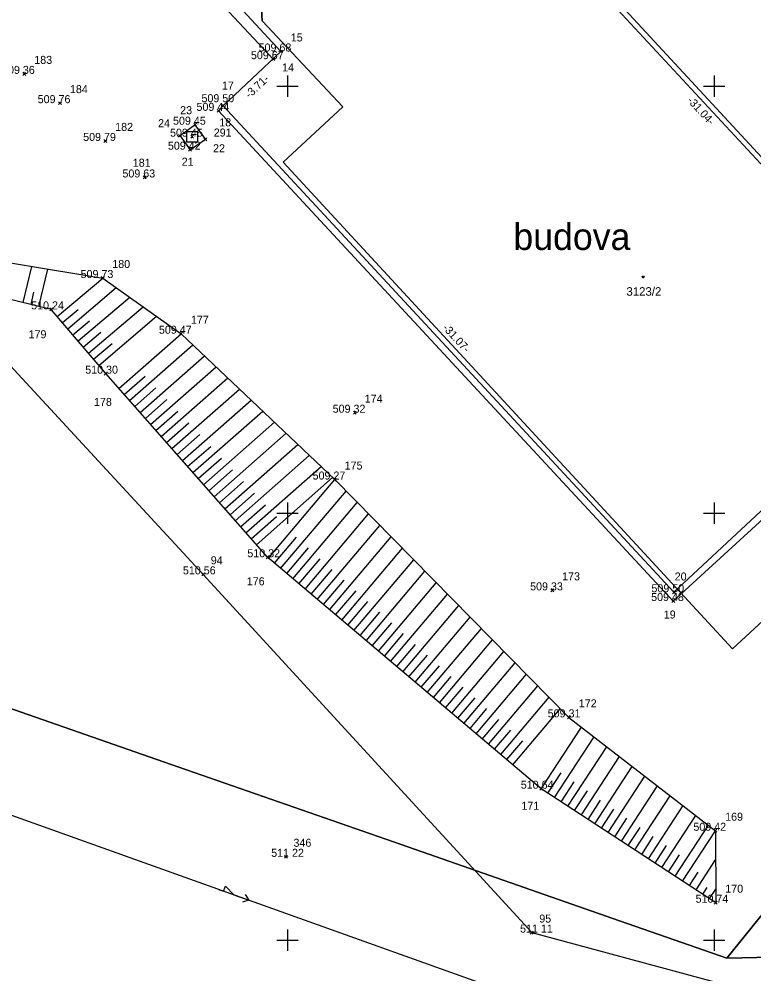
# Model space of a CAD drawing. Extents: x -408550 to -407654, y -1233019 to -1231230.
# Drawn here: x -407992.57 to -407958.14, y -1232101.58 to -1232056.86 of the extents above; entities that cross this region are included whole.
import ezdxf

# ---------------------------------------------------------------- set-up
doc = ezdxf.new("R2010")
doc.units = 0
for name, color, linetype in [('Level 1', 7, 'Continuous'), ('Level 11', 7, 'Continuous'), ('Level 12', 7, 'Continuous'), ('Level 13', 7, 'Continuous'), ('Level 16', 7, 'Continuous'), ('Level 20', 7, 'Continuous'), ('Level 22', 7, 'Continuous'), ('Level 23', 7, 'Continuous'), ('Level 25', 7, 'Continuous'), ('Level 26', 7, 'Continuous'), ('Level 27', 7, 'Continuous'), ('Level 4', 7, 'Continuous'), ('Level 40', 7, 'Continuous')]:
    doc.layers.add(name, color=color, linetype=linetype)

msp = doc.modelspace()

# ---------------------------------------------------------------- linework, layer by layer
at = {"layer": 'Level 1'}
for p, q in [((-407980, -1232059.5), (-407980, -1232060.5)), ((-407960, -1232059.5), (-407960, -1232060.5)), ((-407980.5, -1232060), (-407979.5, -1232060)), ((-407960.5, -1232060), (-407959.5, -1232060)), ((-407980, -1232079.5), (-407980, -1232080.5)), ((-407960, -1232079.5), (-407960, -1232080.5)), ((-407980.5, -1232080), (-407979.5, -1232080)), ((-407960.5, -1232080), (-407959.5, -1232080)), ((-407980, -1232099.5), (-407980, -1232100.5)), ((-407960, -1232099.5), (-407960, -1232100.5)), ((-407980.5, -1232100), (-407979.5, -1232100)), ((-407960.5, -1232100), (-407959.5, -1232100))]:
    msp.add_line(p, q, dxfattribs=at)
for points in [[(-407865.11, -1232098.76), (-407959.41, -1232100.85), (-407908.02, -1232037.31), (-407927.08, -1232021.88), (-407925.98, -1232020.38), (-407922.27, -1232015.79), (-407913.48, -1232004.91), (-407905.89, -1231995.51), (-407896.46, -1231983.85)], [(-407908.02, -1232037.31), (-407959.41, -1232100.85), (-407964.75, -1232098.99), (-407974.67, -1232095.53), (-407985.8, -1232091.65), (-408004.8, -1232085.03), (-408023.96, -1232078.34), (-408035.27, -1232074.4), (-408044.77, -1232071.09)], [(-408044.77, -1232071.09), (-408035.27, -1232074.4), (-408023.96, -1232078.34), (-408004.8, -1232085.03), (-407985.8, -1232091.65), (-407974.67, -1232095.53), (-407964.75, -1232098.99), (-407959.41, -1232100.85), (-407865.11, -1232098.76), (-407866.39, -1232098.97), (-407901.79, -1232106.39), (-407899.44, -1232117.51), (-407894.61, -1232140.35), (-407874.15, -1232135.48), (-407862.74, -1232131.55), (-407855.39, -1232125.61), (-407852.28, -1232122.69), (-407848.72, -1232121.07), (-407838.47, -1232120.5), (-407847.32, -1232123.67), (-407848.36, -1232134.5), (-407841.61, -1232145.17), (-407846.34, -1232175.35)]]:
    msp.add_lwpolyline(points, dxfattribs=at)
for points in [[(-407983.55, -1232015.52), (-407983.6, -1232014.52), (-407981.73, -1232014.41), (-407981.67, -1232015.42), (-407970.32, -1232014.9), (-407969.16, -1232040.17), (-407975.2, -1232040.45), (-407974.95, -1232045.12), (-407973.55, -1232045.08), (-407973.31, -1232049.36), (-407974.72, -1232049.44), (-407974.48, -1232053.95), (-407972.3, -1232056.28), (-407968.04, -1232052.23), (-407946.92, -1232075.07), (-407959.14, -1232086.36), (-407980.2, -1232063.57), (-407977.4, -1232060.97), (-407981.18, -1232056.94), (-407981.8, -1232045.69), (-407982.07, -1232040.75), (-407985.47, -1232040.9), (-407986.59, -1232015.66)], [(-407983.6, -1232014.52), (-407983.55, -1232015.52), (-407986.59, -1232015.66), (-407985.47, -1232040.9), (-407982.07, -1232040.75), (-407981.8, -1232045.69), (-407981.18, -1232056.94), (-407977.4, -1232060.97), (-407980.2, -1232063.57), (-407959.14, -1232086.36), (-407946.92, -1232075.07), (-407968.04, -1232052.23), (-407972.3, -1232056.28), (-407974.48, -1232053.95), (-407974.72, -1232049.44), (-407973.31, -1232049.36), (-407973.55, -1232045.08), (-407974.95, -1232045.12), (-407975.2, -1232040.45), (-407969.16, -1232040.17), (-407970.32, -1232014.9), (-407981.67, -1232015.42), (-407981.73, -1232014.41)], [(-407963.309, -1232068.905), (-407963.287, -1232068.943), (-407963.309, -1232068.981), (-407963.352, -1232068.981), (-407963.374, -1232068.943), (-407963.352, -1232068.905)]]:
    msp.add_lwpolyline(points, close=True, dxfattribs=at)
at = {"layer": 'Level 11'}
msp.add_lwpolyline([(-407989.46, -1232013.01), (-407973.21, -1232012.23), (-407971.98, -1232037.5), (-407977.95, -1232037.78), (-407977.733, -1232042.415), (-407976.39, -1232042.37), (-407976.14, -1232046.74), (-407977.45, -1232046.87), (-407977.009, -1232051.318), (-407974.962, -1232053.765), (-407970.82, -1232049.62), (-407949.71, -1232072.37), (-407961.89, -1232083.71), (-407983.01, -1232060.92), (-407980.3, -1232058.38), (-407984.06, -1232054.32), (-407985.01, -1232038.14), (-407988.32, -1232038.28)], close=True, dxfattribs=at)
at = {"layer": 'Level 12'}
msp.add_lwpolyline([(-408056.73, -1232038.31), (-408035.18, -1232049.43), (-408016.67, -1232058.98), (-407995.64, -1232070.23), (-407983.94, -1232082.87), (-407968.55, -1232099.65), (-407955.47, -1232103.17), (-407935.56, -1232108.32), (-407927.78, -1232110.15), (-407922.43, -1232090.45), (-407918.07, -1232073.76), (-407912.71, -1232053.79), (-407910.82, -1232047.19), (-407908.67, -1232042.13), (-407906.88, -1232038.31), (-407908.34, -1232037.12), (-407921.23, -1232026.55), (-407939.09, -1232011.64)], dxfattribs=at)
at = {"layer": 'Level 13'}
for p, q in [((-407992.374, -1232070.143), (-407991.965, -1232068.448)), ((-407992.374, -1232070.143), (-407991.965, -1232068.448)), ((-407991.644, -1232070.319), (-407991.223, -1232068.569)), ((-407991.644, -1232070.319), (-407991.223, -1232068.569)), ((-407990.778, -1232070.793), (-407988.65, -1232068.99)), ((-407992.009, -1232070.231), (-407991.871, -1232069.657)), ((-407992.009, -1232070.231), (-407991.871, -1232069.657)), ((-407990.293, -1232071.365), (-407988.019, -1232069.439)), ((-407989.808, -1232071.937), (-407987.388, -1232069.887)), ((-407990.536, -1232071.079), (-407989.803, -1232070.458)), ((-407989.324, -1232072.51), (-407986.758, -1232070.336)), ((-407990.051, -1232071.651), (-407989.269, -1232070.989)), ((-407988.839, -1232073.082), (-407986.127, -1232070.784)), ((-407989.566, -1232072.223), (-407988.736, -1232071.52)), ((-407987.894, -1232074.169), (-407984.98, -1232071.6)), ((-407989.081, -1232072.796), (-407988.202, -1232072.051)), ((-407987.398, -1232074.731), (-407984.434, -1232072.118)), ((-407986.902, -1232075.294), (-407983.887, -1232072.636)), ((-407986.407, -1232075.857), (-407983.341, -1232073.155)), ((-407987.646, -1232074.45), (-407986.667, -1232073.587)), ((-407985.911, -1232076.419), (-407982.795, -1232073.673)), ((-407987.15, -1232075.013), (-407986.155, -1232074.135)), ((-407985.415, -1232076.982), (-407982.248, -1232074.191)), ((-407986.654, -1232075.575), (-407985.642, -1232074.683)), ((-407984.919, -1232077.544), (-407981.702, -1232074.709)), ((-407986.159, -1232076.138), (-407985.129, -1232075.231)), ((-407984.423, -1232078.107), (-407981.156, -1232075.228)), ((-407985.663, -1232076.701), (-407984.617, -1232075.779)), ((-407983.927, -1232078.67), (-407980.61, -1232075.746)), ((-407985.167, -1232077.263), (-407984.104, -1232076.326)), ((-407983.431, -1232079.232), (-407980.063, -1232076.264)), ((-407984.671, -1232077.826), (-407983.591, -1232076.874)), ((-407982.935, -1232079.795), (-407979.517, -1232076.782)), ((-407982.439, -1232080.358), (-407978.971, -1232077.301)), ((-407984.175, -1232078.388), (-407983.079, -1232077.422)), ((-407981.943, -1232080.92), (-407978.424, -1232077.819)), ((-407983.679, -1232078.951), (-407982.566, -1232077.97)), ((-407983.183, -1232079.514), (-407982.053, -1232078.518)), ((-407981.447, -1232081.483), (-407977.878, -1232078.337)), ((-407980.888, -1232082.106), (-407977.78, -1232078.43)), ((-407980.888, -1232082.106), (-407977.78, -1232078.43)), ((-407982.687, -1232080.076), (-407981.541, -1232079.066)), ((-407980.315, -1232082.59), (-407977.252, -1232078.967)), ((-407980.315, -1232082.59), (-407977.252, -1232078.967)), ((-407979.742, -1232083.074), (-407976.723, -1232079.503)), ((-407979.742, -1232083.074), (-407976.723, -1232079.503)), ((-407982.191, -1232080.639), (-407981.028, -1232079.614)), ((-407979.17, -1232083.558), (-407976.195, -1232080.04)), ((-407979.17, -1232083.558), (-407976.195, -1232080.04)), ((-407981.695, -1232081.202), (-407980.515, -1232080.161)), ((-407978.597, -1232084.043), (-407975.666, -1232080.576)), ((-407978.597, -1232084.043), (-407975.666, -1232080.576)), ((-407980.602, -1232082.348), (-407979.574, -1232081.132)), ((-407980.602, -1232082.348), (-407979.574, -1232081.132)), ((-407978.024, -1232084.527), (-407975.138, -1232081.113)), ((-407978.024, -1232084.527), (-407975.138, -1232081.113)), ((-407980.029, -1232082.832), (-407979.016, -1232081.634)), ((-407980.029, -1232082.832), (-407979.016, -1232081.634)), ((-407977.452, -1232085.011), (-407974.609, -1232081.65)), ((-407977.452, -1232085.011), (-407974.609, -1232081.65)), ((-407979.456, -1232083.316), (-407978.458, -1232082.136)), ((-407979.456, -1232083.316), (-407978.458, -1232082.136)), ((-407976.879, -1232085.495), (-407974.081, -1232082.186)), ((-407976.879, -1232085.495), (-407974.081, -1232082.186)), ((-407978.883, -1232083.8), (-407977.9, -1232082.638)), ((-407978.883, -1232083.8), (-407977.9, -1232082.638)), ((-407976.306, -1232085.98), (-407973.553, -1232082.723)), ((-407976.306, -1232085.98), (-407973.553, -1232082.723)), ((-407978.311, -1232084.285), (-407977.342, -1232083.139)), ((-407978.311, -1232084.285), (-407977.342, -1232083.139)), ((-407975.734, -1232086.464), (-407973.024, -1232083.26)), ((-407975.734, -1232086.464), (-407973.024, -1232083.26)), ((-407977.738, -1232084.769), (-407976.784, -1232083.641)), ((-407977.738, -1232084.769), (-407976.784, -1232083.641)), ((-407975.161, -1232086.948), (-407972.496, -1232083.796)), ((-407975.161, -1232086.948), (-407972.496, -1232083.796)), ((-407977.165, -1232085.253), (-407976.226, -1232084.143)), ((-407977.165, -1232085.253), (-407976.226, -1232084.143)), ((-407974.588, -1232087.432), (-407971.967, -1232084.333)), ((-407974.588, -1232087.432), (-407971.967, -1232084.333)), ((-407976.593, -1232085.738), (-407975.668, -1232084.644)), ((-407976.593, -1232085.738), (-407975.668, -1232084.644)), ((-407974.015, -1232087.917), (-407971.439, -1232084.869)), ((-407974.015, -1232087.917), (-407971.439, -1232084.869)), ((-407976.02, -1232086.222), (-407975.11, -1232085.146)), ((-407976.02, -1232086.222), (-407975.11, -1232085.146)), ((-407973.443, -1232088.401), (-407970.91, -1232085.406)), ((-407973.443, -1232088.401), (-407970.91, -1232085.406)), ((-407975.447, -1232086.706), (-407974.552, -1232085.648)), ((-407975.447, -1232086.706), (-407974.552, -1232085.648)), ((-407974.874, -1232087.19), (-407973.994, -1232086.149)), ((-407974.874, -1232087.19), (-407973.994, -1232086.149)), ((-407972.87, -1232088.885), (-407970.382, -1232085.943)), ((-407972.87, -1232088.885), (-407970.382, -1232085.943)), ((-407974.302, -1232087.675), (-407973.436, -1232086.651)), ((-407974.302, -1232087.675), (-407973.436, -1232086.651)), ((-407972.297, -1232089.369), (-407969.854, -1232086.479)), ((-407972.297, -1232089.369), (-407969.854, -1232086.479)), ((-407973.729, -1232088.159), (-407972.878, -1232087.153)), ((-407973.729, -1232088.159), (-407972.878, -1232087.153)), ((-407971.725, -1232089.854), (-407969.325, -1232087.016)), ((-407971.725, -1232089.854), (-407969.325, -1232087.016)), ((-407973.156, -1232088.643), (-407972.32, -1232087.654)), ((-407973.156, -1232088.643), (-407972.32, -1232087.654)), ((-407971.152, -1232090.338), (-407968.797, -1232087.553)), ((-407971.152, -1232090.338), (-407968.797, -1232087.553)), ((-407970.579, -1232090.822), (-407968.268, -1232088.089)), ((-407970.579, -1232090.822), (-407968.268, -1232088.089)), ((-407972.584, -1232089.127), (-407971.762, -1232088.156)), ((-407972.584, -1232089.127), (-407971.762, -1232088.156)), ((-407972.011, -1232089.612), (-407971.205, -1232088.658)), ((-407972.011, -1232089.612), (-407971.205, -1232088.658)), ((-407970.006, -1232091.306), (-407967.74, -1232088.626)), ((-407970.006, -1232091.306), (-407967.74, -1232088.626)), ((-407971.438, -1232090.096), (-407970.647, -1232089.16)), ((-407971.438, -1232090.096), (-407970.647, -1232089.16)), ((-407969.434, -1232091.791), (-407967.211, -1232089.162)), ((-407969.434, -1232091.791), (-407967.211, -1232089.162)), ((-407970.865, -1232090.58), (-407970.089, -1232089.661)), ((-407970.865, -1232090.58), (-407970.089, -1232089.661)), ((-407970.293, -1232091.064), (-407969.531, -1232090.163)), ((-407970.293, -1232091.064), (-407969.531, -1232090.163)), ((-407968.11, -1232092.91), (-407966.225, -1232090.022)), ((-407969.72, -1232091.549), (-407968.973, -1232090.665)), ((-407969.72, -1232091.549), (-407968.973, -1232090.665)), ((-407967.482, -1232093.32), (-407965.63, -1232090.482)), ((-407966.854, -1232093.73), (-407965.034, -1232090.943)), ((-407966.226, -1232094.14), (-407964.439, -1232091.403)), ((-407965.598, -1232094.55), (-407963.844, -1232091.863)), ((-407967.796, -1232093.115), (-407967.174, -1232092.162)), ((-407964.97, -1232094.96), (-407963.248, -1232092.323)), ((-407967.168, -1232093.525), (-407966.557, -1232092.588)), ((-407966.54, -1232093.935), (-407965.939, -1232093.015)), ((-407964.342, -1232095.37), (-407962.653, -1232092.783)), ((-407965.912, -1232094.345), (-407965.322, -1232093.442)), ((-407963.714, -1232095.78), (-407962.058, -1232093.243)), ((-407965.284, -1232094.755), (-407964.705, -1232093.868)), ((-407963.086, -1232096.19), (-407961.462, -1232093.703)), ((-407964.656, -1232095.165), (-407964.088, -1232094.295)), ((-407962.458, -1232096.6), (-407960.867, -1232094.163)), ((-407964.028, -1232095.575), (-407963.471, -1232094.722)), ((-407961.83, -1232097.01), (-407960.272, -1232094.623)), ((-407963.4, -1232095.985), (-407962.854, -1232095.148)), ((-407961.48, -1232097.238), (-407959.94, -1232094.88)), ((-407962.772, -1232096.395), (-407962.237, -1232095.575)), ((-407962.144, -1232096.805), (-407961.62, -1232096.002)), ((-407960.852, -1232097.648), (-407959.936, -1232096.246)), ((-407961.166, -1232097.443), (-407960.757, -1232096.817)), ((-407960.538, -1232097.853), (-407960.337, -1232097.545)), ((-407960.224, -1232098.058), (-407959.932, -1232097.612))]:
    msp.add_line(p, q, dxfattribs=at)
msp.add_lwpolyline([(-408016.03, -1232057.25), (-408005.35, -1232062.86), (-407996.29, -1232067.74), (-407988.65, -1232068.99), (-407984.98, -1232071.6), (-407977.78, -1232078.43), (-407966.81, -1232089.57), (-407959.94, -1232094.88), (-407959.93, -1232098.25), (-407968.11, -1232092.91), (-407980.93, -1232082.07), (-407988.51, -1232073.47), (-407991.06, -1232070.46), (-407995.29, -1232069.44), (-408005.7, -1232063.98), (-408016.05, -1232058.27)], close=True, dxfattribs=at)
at = {"layer": 'Level 16'}
for points in [[(-407985.48, -1232038.14), (-407985.17, -1232043.03), (-407986.15, -1232043.11), (-407986.09, -1232044.7), (-407985.1, -1232044.65), (-407984.84, -1232049.89), (-407985.81, -1232049.99), (-407985.66, -1232052.34), (-407984.68, -1232052.31), (-407984.56, -1232054.57), (-407980.66, -1232058.74)], [(-407983.01, -1232060.92), (-407983.22, -1232061.16), (-407961.92, -1232084.12), (-407956.419, -1232079.076), (-407955.74, -1232079.81), (-407953.74, -1232077.96), (-407954.623, -1232077.006)]]:
    msp.add_lwpolyline(points, dxfattribs=at)
msp.add_lwpolyline([(-407985.03, -1232062.33), (-407984.56, -1232062.98), (-407983.84, -1232062.49), (-407984.32, -1232061.81)], close=True, dxfattribs=at)
at = {"layer": 'Level 20'}
msp.add_lwpolyline([(-407984.71, -1232062.12), (-407984.21, -1232062.12), (-407984.21, -1232062.62), (-407984.71, -1232062.62)], close=True, dxfattribs=at)
at = {"layer": 'Level 22'}
msp.add_lwpolyline([(-408151.19, -1232037.68), (-408071.39, -1232066.44), (-407993.81, -1232093.84), (-407921.31, -1232119.76), (-407919.17, -1232112.74), (-407917.389, -1232106.855)], dxfattribs=at)
at = {"layer": 'Level 23'}
for points in [[(-407980.231, -1232058.449), (-407980.369, -1232058.311)], [(-407980.369, -1232058.449), (-407980.231, -1232058.311)], [(-407980.591, -1232058.809), (-407980.729, -1232058.671)], [(-407980.729, -1232058.809), (-407980.591, -1232058.671)], [(-407992.251, -1232059.499), (-407992.389, -1232059.361)], [(-407992.389, -1232059.499), (-407992.251, -1232059.361)], [(-407990.581, -1232060.869), (-407990.719, -1232060.731)], [(-407990.719, -1232060.869), (-407990.581, -1232060.731)], [(-407983.151, -1232061.229), (-407983.289, -1232061.091)], [(-407983.289, -1232061.229), (-407983.151, -1232061.091)], [(-407982.941, -1232060.989), (-407983.079, -1232060.851)], [(-407983.079, -1232060.989), (-407982.941, -1232060.851)], [(-407984.251, -1232061.879), (-407984.389, -1232061.741)], [(-407984.389, -1232061.879), (-407984.251, -1232061.741)], [(-407988.461, -1232062.639), (-407988.599, -1232062.501)], [(-407988.599, -1232062.639), (-407988.461, -1232062.501)], [(-407984.961, -1232062.399), (-407985.099, -1232062.261)], [(-407985.099, -1232062.399), (-407984.961, -1232062.261)], [(-407984.391, -1232062.439), (-407984.529, -1232062.301)], [(-407984.529, -1232062.439), (-407984.391, -1232062.301)], [(-407983.771, -1232062.559), (-407983.909, -1232062.421)], [(-407983.909, -1232062.559), (-407983.771, -1232062.421)], [(-407984.491, -1232063.049), (-407984.629, -1232062.911)], [(-407984.629, -1232063.049), (-407984.491, -1232062.911)], [(-407986.611, -1232064.349), (-407986.749, -1232064.211)], [(-407986.749, -1232064.349), (-407986.611, -1232064.211)], [(-407988.581, -1232069.059), (-407988.719, -1232068.921)], [(-407988.719, -1232069.059), (-407988.581, -1232068.921)], [(-407990.991, -1232070.529), (-407991.129, -1232070.391)], [(-407991.129, -1232070.529), (-407990.991, -1232070.391)], [(-407984.911, -1232071.669), (-407985.049, -1232071.531)], [(-407985.049, -1232071.669), (-407984.911, -1232071.531)], [(-407988.441, -1232073.539), (-407988.579, -1232073.401)], [(-407988.579, -1232073.539), (-407988.441, -1232073.401)], [(-407976.771, -1232075.369), (-407976.909, -1232075.231)], [(-407976.909, -1232075.369), (-407976.771, -1232075.231)], [(-407977.711, -1232078.499), (-407977.849, -1232078.361)], [(-407977.849, -1232078.499), (-407977.711, -1232078.361)], [(-407980.861, -1232082.139), (-407980.999, -1232082.001)], [(-407980.999, -1232082.139), (-407980.861, -1232082.001)], [(-407983.871, -1232082.939), (-407984.009, -1232082.801)], [(-407984.009, -1232082.939), (-407983.871, -1232082.801)], [(-407967.521, -1232083.689), (-407967.659, -1232083.551)], [(-407967.659, -1232083.689), (-407967.521, -1232083.551)], [(-407961.851, -1232084.189), (-407961.989, -1232084.051)], [(-407961.989, -1232084.189), (-407961.851, -1232084.051)], [(-407961.821, -1232083.779), (-407961.959, -1232083.641)], [(-407961.959, -1232083.779), (-407961.821, -1232083.641)], [(-407966.741, -1232089.639), (-407966.879, -1232089.501)], [(-407966.879, -1232089.639), (-407966.741, -1232089.501)], [(-407968.041, -1232092.979), (-407968.179, -1232092.841)], [(-407968.179, -1232092.979), (-407968.041, -1232092.841)], [(-407959.871, -1232094.949), (-407960.009, -1232094.811)], [(-407960.009, -1232094.949), (-407959.871, -1232094.811)], [(-407979.991, -1232096.169), (-407980.129, -1232096.031)], [(-407980.129, -1232096.169), (-407979.991, -1232096.031)], [(-407959.861, -1232098.319), (-407959.999, -1232098.181)], [(-407959.999, -1232098.319), (-407959.861, -1232098.181)], [(-407968.481, -1232099.719), (-407968.619, -1232099.581)], [(-407968.619, -1232099.719), (-407968.481, -1232099.581)]]:
    msp.add_lwpolyline(points, dxfattribs=at)
at = {"layer": 'Level 25'}
for points in [[(-407983.22, -1232097.627), (-407982.985, -1232097.711), (-407982.9, -1232097.476), (-407982.514, -1232097.88), (-407981.807, -1232098.132)], [(-407981.98, -1232097.871), (-407981.807, -1232098.132), (-407982.106, -1232098.224)]]:
    msp.add_lwpolyline(points, dxfattribs=at)
at = {"layer": 'Level 4'}
msp.add_lwpolyline([(-407823.58, -1231999.5), (-407837.41, -1231987.92), (-407838.34, -1231987.97), (-407840.86, -1231988.11), (-407842.83, -1231990.51), (-407843.19, -1231994.63), (-407839.56, -1232019.93), (-407835.24, -1232048.6), (-407834.29, -1232054.76), (-407828.44, -1232092.63), (-407834.82, -1232093.74), (-407838.8, -1232094.4), (-407843.51, -1232095.18), (-407846.32, -1232095.65), (-407865.11, -1232098.76), (-407959.41, -1232100.85), (-407964.75, -1232098.99), (-407974.67, -1232095.53), (-407985.8, -1232091.65), (-408004.8, -1232085.03), (-408023.96, -1232078.34), (-408035.27, -1232074.4), (-408044.77, -1232071.09)], dxfattribs=at)

# ---------------------------------------------------------------- texts
at = {"layer": 'Level 1'}
for s, rotation, p in [('-3.71-', 43.1437, (-407981.776, -1232060.596)), ('-31.04-', 312.8456, (-407961.294, -1232060.695)), ('-31.07-', 312.8456, (-407972.757, -1232071.345))]:
    msp.add_text(s, height=0.375, rotation=rotation, dxfattribs=at).set_placement(p)
msp.add_text('3123/2', height=0.4, dxfattribs=at).set_placement((-407964.115, -1232069.82))
at = {"layer": 'Level 26'}
for s, p in [('15', (-407979.839, -1232057.91)), ('183', (-407991.857, -1232058.96)), ('14', (-407980.245, -1232059.312)), ('17', (-407983.066, -1232060.164)), ('184', (-407990.187, -1232060.33)), ('23', (-407985.023, -1232061.317)), ('182', (-407988.067, -1232062.1)), ('24', (-407986.056, -1232061.926)), ('18', (-407983.189, -1232061.888)), ('291', (-407983.448, -1232062.363)), ('22', (-407983.481, -1232063.099)), ('181', (-407987.242, -1232063.777)), ('21', (-407984.949, -1232063.731)), ('180', (-407988.203, -1232068.52)), ('177', (-407984.517, -1232071.13)), ('179', (-407992.124, -1232071.812)), ('178', (-407989.059, -1232074.981)), ('174', (-407976.377, -1232074.83)), ('175', (-407977.317, -1232077.96)), ('94', (-407983.587, -1232082.4)), ('176', (-407981.901, -1232083.382)), ('173', (-407967.127, -1232083.15)), ('20', (-407961.853, -1232083.157)), ('19', (-407962.365, -1232084.939)), ('172', (-407966.347, -1232089.1)), ('171', (-407969.033, -1232093.894)), ('169', (-407959.489, -1232094.41)), ('346', (-407979.714, -1232095.63)), ('170', (-407959.483, -1232097.78)), ('95', (-407968.197, -1232099.18))]:
    msp.add_text(s, height=0.375, dxfattribs=at).set_placement(p)
at = {"layer": 'Level 27'}
msp.add_text('budova', height=1.25, dxfattribs=at).set_placement((-407969.411, -1232067.676))
at = {"layer": 'Level 40'}
for s, p in [('509 68', (-407981.347, -1232058.38)), ('509 67', (-407981.707, -1232058.74)), ('509 36', (-407993.367, -1232059.43)), ('509 50', (-407984.024, -1232060.756)), ('509 76', (-407991.697, -1232060.8)), ('509 44', (-407984.257, -1232061.16)), ('509 45', (-407985.357, -1232061.81)), ('509 45', (-407985.497, -1232062.37)), ('509 79', (-407989.568, -1232062.57)), ('509 42', (-407985.597, -1232062.98)), ('509 63', (-407987.727, -1232064.28)), ('509 73', (-407989.687, -1232068.99)), ('510 24', (-407992.004, -1232070.46)), ('509 47', (-407986.017, -1232071.6)), ('510 30', (-407989.47, -1232073.47)), ('509 32', (-407977.877, -1232075.3)), ('509 27', (-407978.817, -1232078.43)), ('510 32', (-407981.874, -1232082.07)), ('510 56', (-407984.894, -1232082.87)), ('509 33', (-407968.627, -1232083.62)), ('509 50', (-407962.943, -1232083.71)), ('509 48', (-407962.957, -1232084.12)), ('509 31', (-407967.803, -1232089.57)), ('510 64', (-407969.064, -1232092.91)), ('509 42', (-407960.977, -1232094.88)), ('511 22', (-407980.759, -1232096.1)), ('510 74', (-407960.874, -1232098.25)), ('511 11', (-407969.098, -1232099.65))]:
    msp.add_text(s, height=0.375, dxfattribs=at).set_placement(p)

doc.saveas('drawing.dxf')
